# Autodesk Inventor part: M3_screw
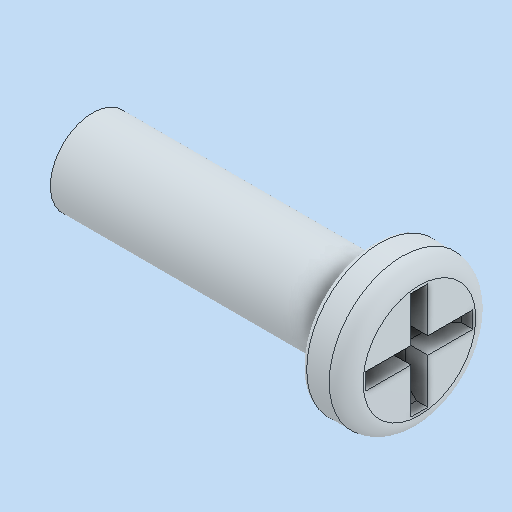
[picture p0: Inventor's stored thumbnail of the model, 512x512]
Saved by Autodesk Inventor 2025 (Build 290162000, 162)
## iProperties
Created: 2025-05
Part Number: M3_screw
Material: Generico
Description: M3_screw
Document SubType Name: Modeling
Designer: R5800u
Density: 1 g/cm^3
Appearance: Default
Author: R5800u
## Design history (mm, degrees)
feature "Base1"
node "Solido1"
